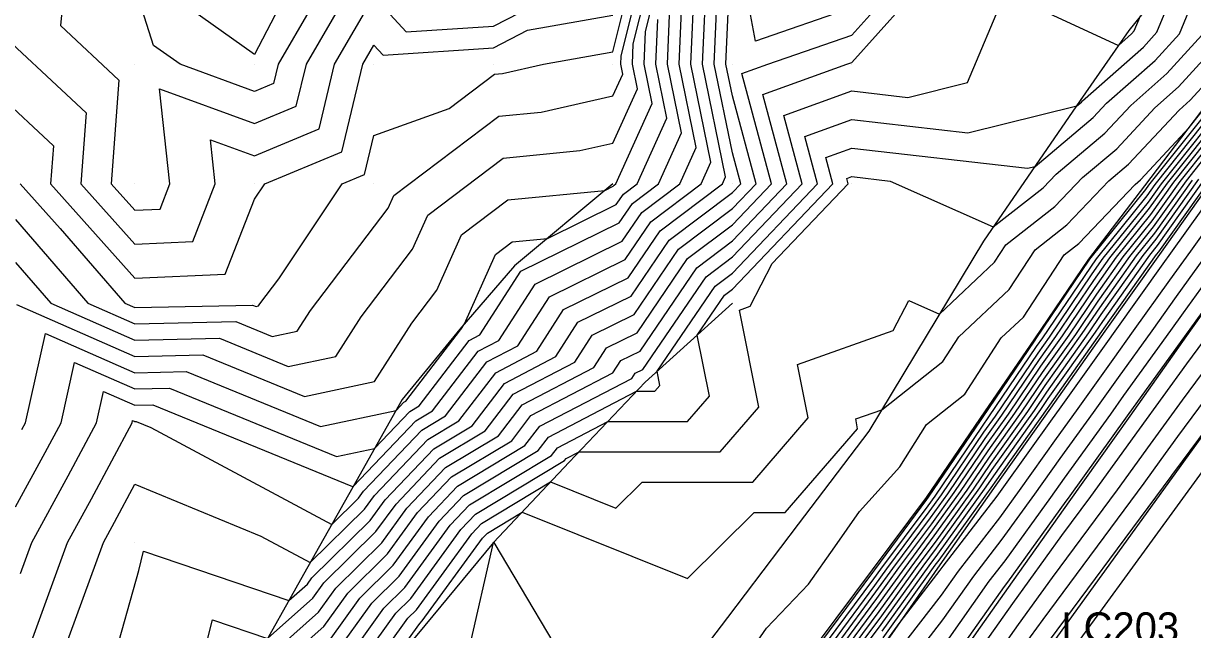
# Model space of a CAD drawing. Extents: x 2188792 to 2191981, y 386090 to 389710.
# Drawn here: x 2190140.8 to 2190238.6, y 387762.9 to 387813.6 of the extents above; entities that cross this region are included whole.
import ezdxf

# ---------------------------------------------------------------- set-up
doc = ezdxf.new("R2010")
doc.units = 0
for name, color, linetype in [('DTM Contours Major', 7, 'Continuous'), ('DTM Contours Minor', 7, 'Continuous'), ('Exist DTM QL2 LIDAR Elevation Point', 7, 'Continuous'), ('Exist Roads EOP', 7, 'Continuous'), ('Exist Roads EOP Cogo Number', 7, 'Continuous'), ('Exist Roads EOT', 7, 'Continuous'), ('PH Exist DTM Breakline', 7, 'Continuous')]:
    doc.layers.add(name, color=color, linetype=linetype)

msp = doc.modelspace()

# ---------------------------------------------------------------- linework, layer by layer
at = {"layer": 'DTM Contours Major'}
for points in [[(2190144.659, 387821.205), (2190143.891, 387813.407), (2190148.79, 387808.85), (2190148.149, 387800.181), (2190150.122, 387797.966), (2190152.238, 387798.064), (2190153.062, 387800.181), (2190152.187, 387808.117), (2190160.123, 387805.211), (2190163.634, 387806.67), (2190164.473, 387810.182), (2190170.124, 387819.904)], [(2190140.121, 387793.604), (2190143.09, 387790.18), (2190150.122, 387787.092), (2190157.192, 387787.249), (2190162.959, 387784.89), (2190166.936, 387785.738), (2190169.059, 387789.052), (2190173.364, 387794.707), (2190174.628, 387797.556), (2190180.952, 387802.329), (2190187.353, 387802.953), (2190190.126, 387803.582), (2190192.176, 387808.131), (2190191.756, 387810.182), (2190191.831, 387811.887), (2190193.9, 387820.182)], [(2190161.758, 387759.424), (2190165.94, 387763.142), (2190167.941, 387765.933), (2190171.266, 387769.214), (2190173.786, 387772.672), (2190176.627, 387775.647), (2190181.657, 387778.683), (2190183.264, 387780.783), (2190190.118, 387784.352), (2190190.785, 387785.392), (2190192.394, 387786.181), (2190197.148, 387793.158), (2190200.127, 387795.407), (2190204.671, 387800.181), (2190202.666, 387807.642), (2190209.704, 387810.182), (2190210.127, 387810.327), (2190218.922, 387820.182)], [(2190141.468, 387761.877), (2190144.498, 387770.178), (2190146.492, 387773.807), (2190149.89, 387780.179), (2190149.932, 387780.368), (2190150.122, 387780.285), (2190150.23, 387780.287), (2190151.458, 387779.785), (2190166.597, 387771.665), (2190168.844, 387773.883), (2190169.259, 387774.453), (2190174.129, 387779.552), (2190176.123, 387780.756), (2190179.579, 387785.27), (2190182.177, 387786.623), (2190184.807, 387790.725), (2190191.153, 387793.839), (2190193.307, 387796.999), (2190197.519, 387800.181), (2190198.329, 387801.978), (2190196.649, 387810.182), (2190196.95, 387817.006)], [(2190168.24, 387757.247), (2190172.953, 387763.82), (2190173.687, 387764.544), (2190178.313, 387770.891), (2190179.125, 387771.741), (2190184.913, 387775.234), (2190190.372, 387773.048), (2190192.575, 387775.223), (2190201.825, 387775.21), (2190206.472, 387780.593), (2190205.586, 387785.062), (2190213.59, 387787.9), (2190214.886, 387790.417), (2190217.447, 387789.267), (2190222.066, 387793.625), (2190223.01, 387795.063), (2190227.116, 387798.278), (2190229.423, 387800.702), (2190232.293, 387803.111), (2190235.478, 387806.533), (2190237.455, 387808.28), (2190241.305, 387812.487)], [(2190208.488, 387761.771), (2190212.052, 387766.571), (2190213.051, 387767.958), (2190216.6, 387772.738), (2190217.615, 387774.148), (2190221.165, 387779.386), (2190222.132, 387780.747), (2190225.7, 387786.014), (2190226.648, 387787.346), (2190230.235, 387792.643), (2190231.164, 387793.948), (2190234.932, 387798.65), (2190236.019, 387800.178), (2190239.618, 387804.692)], [(2190210.876, 387761.68), (2190212.479, 387763.839), (2190215.582, 387768.147), (2190217.111, 387770.206), (2190220.299, 387774.635), (2190221.756, 387776.785), (2190224.85, 387781.136), (2190226.31, 387783.291), (2190229.401, 387787.637), (2190230.864, 387789.797), (2190233.952, 387794.139), (2190235.483, 387796.05), (2190238.64, 387800.489)], [(2190213.956, 387761.034), (2190217.629, 387765.763), (2190219.048, 387767.772), (2190222.492, 387772.237), (2190224.138, 387774.52), (2190227.234, 387778.856), (2190228.916, 387781.187), (2190231.984, 387785.483), (2190233.702, 387787.864), (2190236.74, 387792.119), (2190238.495, 387794.551), (2190241.504, 387798.764)], [(2190246.7, 387794.113), (2190237.768, 387782.084), (2190235.087, 387778.379), (2190232.329, 387774.569), (2190226.891, 387767.239), (2190224.046, 387763.305), (2190221.103, 387759.138)]]:
    msp.add_lwpolyline(points, dxfattribs=at)
at = {"layer": 'DTM Contours Minor'}
for points in [[(2190151.692, 387811.752), (2190148.222, 387822.647), (2190152.051, 387828.254), (2190158.548, 387834.983), (2190163.055, 387823.114), (2190167.602, 387820.182), (2190164.877, 387814.936), (2190162.114, 387810.182), (2190161.73, 387808.574), (2190160.123, 387807.906), (2190153.909, 387810.182), (2190151.692, 387811.752)], [(2190160.123, 387810.995), (2190154.743, 387814.803), (2190152.529, 387821.755), (2190154.973, 387825.333), (2190159.118, 387829.626), (2190161.993, 387822.053), (2190164.895, 387820.182), (2190160.123, 387810.995)], [(2190200.553, 387820.182), (2190206.157, 387824.153), (2190210.127, 387827.386), (2190214.853, 387820.182), (2190210.127, 387814.887), (2190202.051, 387812.106), (2190200.553, 387820.182)], [(2190140.121, 387797.18), (2190146.191, 387790.18), (2190150.122, 387788.454), (2190158.584, 387788.641), (2190161.611, 387787.403), (2190163.699, 387787.848), (2190164.814, 387789.588), (2190171.329, 387798.145), (2190171.799, 387799.205), (2190180.583, 387805.835), (2190184.126, 387806.18), (2190190.126, 387807.542), (2190190.946, 387809.361), (2190190.778, 387810.182), (2190190.808, 387810.864), (2190193.131, 387820.182)], [(2190140.224, 387790.077), (2190150.122, 387785.731), (2190155.8, 387785.857), (2190164.306, 387782.377), (2190170.173, 387783.627), (2190173.304, 387788.517), (2190175.399, 387791.269), (2190177.458, 387795.907), (2190181.322, 387798.823), (2190189.448, 387799.615), (2190190.161, 387799.965), (2190190.234, 387800.072), (2190190.377, 387800.181), (2190193.407, 387806.9), (2190192.735, 387810.182), (2190192.855, 387812.911), (2190194.668, 387820.182)], [(2190140.53, 387800.181), (2190143.878, 387796.423), (2190149.292, 387790.18), (2190150.122, 387789.815), (2190159.977, 387790.034), (2190160.264, 387789.916), (2190160.463, 387789.958), (2190160.568, 387790.123), (2190162.17, 387792.227), (2190167.478, 387800.181), (2190169.347, 387800.958), (2190170.124, 387804.211), (2190176.421, 387806.478), (2190180.213, 387809.34), (2190180.899, 387809.407), (2190184.31, 387810.182), (2190190.126, 387811.209), (2190192.363, 387820.182)], [(2190153.979, 387753.161), (2190156.611, 387763.689), (2190161.217, 387762.12), (2190165.021, 387765.501), (2190165.936, 387766.778), (2190170.297, 387771.082), (2190171.975, 387773.385), (2190175.628, 387777.209), (2190179.443, 387779.512), (2190181.79, 387782.578), (2190186.942, 387785.26), (2190188.394, 387787.525), (2190191.898, 387789.244), (2190195.612, 387794.694), (2190200.127, 387798.105), (2190202.103, 387800.181), (2190200.127, 387807.537), (2190199.585, 387810.182), (2190200.021, 387820.077)], [(2190160.581, 387759.966), (2190165.48, 387764.322), (2190166.939, 387766.355), (2190170.781, 387770.148), (2190172.881, 387773.028), (2190176.127, 387776.428), (2190180.55, 387779.098), (2190182.527, 387781.68), (2190188.53, 387784.806), (2190189.59, 387786.458), (2190192.146, 387787.712), (2190196.38, 387793.926), (2190200.127, 387796.756), (2190203.387, 387800.181), (2190200.911, 387809.398), (2190203.083, 387810.182), (2190210.127, 387812.607), (2190216.888, 387820.182)], [(2190146.165, 387752.534), (2190150.45, 387767.809), (2190150.858, 387769.441), (2190163.01, 387765.301), (2190164.561, 387766.68), (2190164.934, 387767.2), (2190169.812, 387772.016), (2190171.07, 387773.741), (2190175.128, 387777.99), (2190178.336, 387779.927), (2190181.053, 387783.475), (2190185.353, 387785.714), (2190187.198, 387788.592), (2190191.65, 387790.776), (2190194.844, 387795.463), (2190200.127, 387799.453), (2190200.819, 387800.181), (2190200.127, 387802.759), (2190198.606, 387810.182), (2190198.997, 387819.053)], [(2190166.86, 387760.784), (2190169.946, 387765.087), (2190172.234, 387767.346), (2190175.597, 387771.959), (2190177.626, 387774.084), (2190183.87, 387777.853), (2190184.738, 387778.988), (2190192.093, 387782.817), (2190193.639, 387782.815), (2190194.064, 387783.307), (2190193.829, 387784.495), (2190198.685, 387791.621), (2190200.127, 387792.71), (2190207.24, 387800.181), (2190206.178, 387804.13), (2190210.127, 387805.555), (2190219.818, 387804.441), (2190228.935, 387806.69), (2190229.326, 387807.019), (2190229.417, 387807.116), (2190234.513, 387811.618), (2190235.644, 387812.855), (2190238.182, 387818.993)], [(2190142.392, 387756.181), (2190147.502, 387770.178), (2190148.431, 387771.868), (2190150.122, 387775.039), (2190160.674, 387770.698), (2190164.804, 387768.483), (2190169.328, 387772.95), (2190170.164, 387774.097), (2190174.628, 387778.771), (2190177.23, 387780.342), (2190180.316, 387784.373), (2190183.765, 387786.169), (2190186.003, 387789.659), (2190191.401, 387792.307), (2190194.075, 387796.231), (2190199.304, 387800.181), (2190199.56, 387800.747), (2190197.628, 387810.182), (2190197.973, 387818.029)], [(2190167.32, 387759.605), (2190170.949, 387764.665), (2190172.719, 387766.412), (2190176.502, 387771.603), (2190178.126, 387773.303), (2190184.977, 387777.439), (2190185.476, 387778.09), (2190189.699, 387780.289), (2190196.368, 387780.28), (2190198.2, 387782.402), (2190197.185, 387787.524), (2190199.453, 387790.853), (2190200.127, 387791.362), (2190208.524, 387800.181), (2190207.934, 387802.374), (2190210.127, 387803.165), (2190224.824, 387801.476), (2190225.447, 387801.63), (2190230.315, 387805.716), (2190231.437, 387806.922), (2190235.494, 387810.505), (2190237.531, 387812.732), (2190239.496, 387817.484)], [(2190137.358, 387814.19), (2190146.048, 387806.107), (2190145.609, 387800.181), (2190150.122, 387795.117), (2190154.962, 387795.341), (2190156.846, 387800.181), (2190156.44, 387803.864), (2190160.123, 387802.515), (2190165.538, 387804.766), (2190166.832, 387810.182), (2190170.124, 387815.846), (2190172.828, 387812.886), (2190180.125, 387813.368), (2190186.713, 387816.77)], [(2190140.543, 387767.574), (2190141.494, 387770.178), (2190144.554, 387775.746), (2190146.917, 387780.179), (2190147.505, 387782.795), (2190150.122, 387781.646), (2190151.623, 387781.68), (2190168.348, 387774.839), (2190168.39, 387774.847), (2190173.629, 387780.334), (2190175.016, 387781.171), (2190178.842, 387786.168), (2190180.588, 387787.077), (2190183.611, 387791.792), (2190190.905, 387795.37), (2190192.539, 387797.768), (2190195.734, 387800.181), (2190197.099, 387803.209), (2190195.671, 387810.182), (2190195.926, 387815.982)], [(2190166.4, 387761.963), (2190168.944, 387765.51), (2190171.75, 387768.28), (2190174.692, 387772.316), (2190177.126, 387774.865), (2190182.763, 387778.268), (2190184.001, 387779.885), (2190191.707, 387783.897), (2190191.981, 387784.325), (2190192.642, 387784.649), (2190197.917, 387792.39), (2190200.127, 387794.059), (2190205.956, 387800.181), (2190204.422, 387805.886), (2190210.127, 387807.945), (2190214.813, 387807.406), (2190219.805, 387808.638), (2190222.939, 387816.157), (2190232.422, 387811.751), (2190233.532, 387812.731), (2190233.757, 387812.977), (2190234.271, 387814.22)], [(2190140.121, 387773.146), (2190142.615, 387777.685), (2190143.945, 387780.179), (2190145.078, 387785.222), (2190150.122, 387783.008), (2190153.015, 387783.072), (2190167, 387777.351), (2190170.183, 387778.029), (2190173.129, 387781.115), (2190173.909, 387781.586), (2190178.105, 387787.065), (2190179, 387787.531), (2190182.416, 387792.859), (2190190.657, 387796.902), (2190191.77, 387798.536), (2190193.948, 387800.181), (2190195.868, 387804.439), (2190194.692, 387810.182), (2190194.902, 387814.958)], [(2190138.637, 387807.707), (2190143.305, 387803.365), (2190143.069, 387800.181), (2190150.122, 387792.267), (2190157.685, 387792.617), (2190160.123, 387798.878), (2190160.992, 387800.181), (2190167.443, 387802.862), (2190169.191, 387810.182), (2190170.124, 387811.787), (2190170.89, 387810.948), (2190180.125, 387811.557), (2190182.97, 387813.027), (2190190.126, 387814.291)], [(2190140.676, 387779.623), (2190140.972, 387780.179), (2190142.651, 387787.649), (2190150.122, 387784.369), (2190154.407, 387784.464), (2190165.653, 387779.864), (2190171.976, 387781.211), (2190172.63, 387781.896), (2190172.803, 387782.001), (2190177.368, 387787.963), (2190177.412, 387787.986), (2190177.71, 387788.45), (2190180.288, 387794.258), (2190181.692, 387795.317), (2190184.644, 387795.605), (2190190.409, 387798.433), (2190191.002, 387799.304), (2190192.163, 387800.181), (2190194.638, 387805.67), (2190193.713, 387810.182), (2190193.879, 387813.935)], [(2190167.78, 387758.426), (2190171.951, 387764.242), (2190173.203, 387765.478), (2190177.408, 387771.247), (2190178.625, 387772.522), (2190186.083, 387777.024), (2190186.213, 387777.193), (2190187.306, 387777.762), (2190199.097, 387777.745), (2190202.336, 387781.497), (2190200.727, 387789.617), (2190201.606, 387789.929), (2190203.442, 387793.495), (2190209.808, 387800.181), (2190209.69, 387800.618), (2190210.127, 387800.776), (2190213.318, 387800.409), (2190221.96, 387796.57), (2190226.117, 387799.825), (2190227.226, 387800.991), (2190231.304, 387804.414), (2190233.457, 387806.727), (2190236.474, 387809.393), (2190239.418, 387812.609)], [(2190170.264, 387758.25), (2190173.956, 387763.397), (2190174.172, 387763.611), (2190179.219, 387770.534), (2190179.625, 387770.959), (2190182.519, 387772.707), (2190196.367, 387767.162), (2190201.957, 387772.679), (2190204.554, 387772.676), (2190210.607, 387779.688), (2190210.445, 387780.507), (2190212.62, 387781.278), (2190217.745, 387785.316), (2190219.076, 387787.369), (2190223.273, 387791.328), (2190225.449, 387794.643), (2190228.115, 387796.731), (2190231.619, 387800.413), (2190233.282, 387801.808), (2190237.498, 387806.338), (2190238.436, 387807.167), (2190243.192, 387812.364)], [(2190201.094, 387760.265), (2190202.983, 387762.997), (2190206.493, 387766.666), (2190208.692, 387769.803), (2190210.761, 387772.756), (2190214.135, 387776.487), (2190216.369, 387780.045), (2190219.57, 387782.567), (2190222.628, 387787.285), (2190224.479, 387789.03), (2190227.889, 387794.223), (2190229.115, 387795.184), (2190233.816, 387800.124), (2190234.27, 387800.505), (2190238.353, 387804.891), (2190239.33, 387806.116)], [(2190207.533, 387761.808), (2190211.881, 387767.664), (2190212.038, 387767.882), (2190216.396, 387773.751), (2190216.542, 387773.954), (2190220.928, 387780.427), (2190221.045, 387780.591), (2190225.456, 387787.103), (2190225.547, 387787.23), (2190229.984, 387793.782), (2190230.048, 387793.872), (2190234.712, 387799.69), (2190234.97, 387800.053), (2190239.426, 387805.642)], [(2190208.011, 387761.79), (2190211.966, 387767.118), (2190212.544, 387767.92), (2190216.498, 387773.244), (2190217.079, 387774.051), (2190221.047, 387779.907), (2190221.588, 387780.669), (2190225.578, 387786.558), (2190226.098, 387787.288), (2190230.11, 387793.212), (2190230.606, 387793.91), (2190234.822, 387799.17), (2190235.494, 387800.116), (2190239.522, 387805.167)], [(2190208.966, 387761.753), (2190212.137, 387766.025), (2190213.557, 387767.996), (2190216.702, 387772.231), (2190218.152, 387774.246), (2190221.283, 387778.866), (2190222.676, 387780.824), (2190225.822, 387785.469), (2190227.199, 387787.405), (2190230.361, 387792.074), (2190231.721, 387793.986), (2190235.042, 387798.13), (2190236.543, 387800.24), (2190239.714, 387804.217)], [(2190209.443, 387761.735), (2190212.223, 387765.478), (2190214.063, 387768.033), (2190216.804, 387771.725), (2190218.689, 387774.343), (2190221.401, 387778.346), (2190223.219, 387780.902), (2190225.944, 387784.924), (2190227.749, 387787.463), (2190230.487, 387791.505), (2190232.279, 387794.024), (2190235.153, 387797.61), (2190237.067, 387800.302), (2190239.81, 387803.742)], [(2190209.921, 387761.717), (2190212.308, 387764.932), (2190214.57, 387768.071), (2190216.907, 387771.219), (2190219.226, 387774.441), (2190221.519, 387777.825), (2190223.763, 387780.98), (2190226.066, 387784.38), (2190228.3, 387787.521), (2190230.612, 387790.935), (2190232.837, 387794.063), (2190235.263, 387797.09), (2190237.592, 387800.365), (2190239.906, 387803.267)], [(2190210.399, 387761.698), (2190212.393, 387764.385), (2190215.076, 387768.109), (2190217.009, 387770.712), (2190219.762, 387774.538), (2190221.637, 387777.305), (2190224.307, 387781.058), (2190226.188, 387783.835), (2190228.85, 387787.579), (2190230.738, 387790.366), (2190233.394, 387794.101), (2190235.373, 387796.57), (2190238.116, 387800.427), (2190240.002, 387802.793)], [(2190212.735, 387762.199), (2190217.101, 387768.26), (2190217.417, 387768.686), (2190221.909, 387774.928), (2190222.11, 387775.224), (2190226.481, 387781.37), (2190226.675, 387781.657), (2190231.053, 387787.812), (2190231.241, 387788.089), (2190235.625, 387794.253), (2190235.814, 387794.489), (2190240.214, 387800.676)], [(2190211.354, 387761.662), (2190212.564, 387763.292), (2190216.088, 387768.185), (2190217.213, 387769.699), (2190220.836, 387774.733), (2190221.874, 387776.264), (2190225.394, 387781.214), (2190226.432, 387782.746), (2190229.952, 387787.696), (2190230.989, 387789.228), (2190234.51, 387794.177), (2190235.594, 387795.53), (2190239.165, 387800.551)], [(2190212.65, 387762.746), (2190216.595, 387768.222), (2190217.315, 387769.193), (2190221.373, 387774.83), (2190221.992, 387775.744), (2190225.937, 387781.292), (2190226.553, 387782.201), (2190230.502, 387787.754), (2190231.115, 387788.658), (2190235.067, 387794.215), (2190235.704, 387795.01), (2190239.689, 387800.614)], [(2190212.82, 387761.653), (2190214.159, 387763.512), (2190217.521, 387767.839), (2190217.774, 387768.197), (2190222.278, 387774.037), (2190222.842, 387774.819), (2190226.908, 387780.512), (2190227.497, 387781.329), (2190231.542, 387786.994), (2190232.158, 387787.847), (2190236.183, 387793.483), (2190236.825, 387794.372), (2190240.828, 387799.978)], [(2190224.536, 387761.542), (2190226.123, 387763.736), (2190234.571, 387775.124), (2190236.01, 387777.112), (2190237.408, 387779.043), (2190250.996, 387797.344)], [(2190241.836, 387794.908), (2190237.856, 387789.391), (2190236.789, 387787.897), (2190232.866, 387782.46), (2190231.754, 387780.902), (2190227.888, 387775.542), (2190226.731, 387773.922), (2190222.92, 387768.638), (2190221.595, 387766.921), (2190217.846, 387761.61)], [(2190243.506, 387795.087), (2190238.413, 387788.027), (2190238.333, 387787.914), (2190233.308, 387780.948), (2190233.173, 387780.76), (2190228.215, 387773.886), (2190228.027, 387773.623), (2190223.134, 387766.839), (2190222.869, 387766.495), (2190217.954, 387759.534)], [(2190215.192, 387760.409), (2190217.737, 387763.686), (2190220.322, 387767.346), (2190222.706, 387770.438), (2190225.434, 387774.221), (2190227.561, 387777.199), (2190230.335, 387781.044), (2190232.425, 387783.971), (2190235.245, 387787.881), (2190237.298, 387790.755), (2190240.165, 387794.729)], [(2190242.404, 387790.882), (2190238.128, 387785.124), (2190234.164, 387779.647), (2190230.086, 387774.013), (2190227.659, 387770.741), (2190223.556, 387765.067), (2190219.311, 387759.057)], [(2190243.23, 387784.33), (2190237.048, 387776.003), (2190236.932, 387775.844), (2190236.814, 387775.68), (2190225.355, 387760.234)], [(2190178.103, 387761.247), (2190180.12, 387770.172), (2190180.124, 387770.178), (2190180.124, 387770.178)], [(2190180.124, 387770.178), (2190180.126, 387770.179), (2190180.147, 387770.171), (2190180.149, 387770.153), (2190187.392, 387758.002)]]:
    msp.add_lwpolyline(points, dxfattribs=at)
at = {"layer": 'Exist DTM QL2 LIDAR Elevation Point'}
for p, q in [((2190150.122, 387810.182), (2190150.122, 387810.182)), ((2190160.123, 387810.182), (2190160.123, 387810.182)), ((2190170.124, 387810.182), (2190170.124, 387810.182)), ((2190180.125, 387810.182), (2190180.125, 387810.182)), ((2190190.126, 387810.182), (2190190.126, 387810.182)), ((2190200.127, 387810.182), (2190200.127, 387810.182)), ((2190210.127, 387810.182), (2190210.127, 387810.182)), ((2190150.122, 387800.181), (2190150.122, 387800.181)), ((2190160.123, 387800.181), (2190160.123, 387800.181)), ((2190170.124, 387800.181), (2190170.124, 387800.181)), ((2190200.127, 387800.181), (2190200.127, 387800.181)), ((2190210.127, 387800.181), (2190210.127, 387800.181)), ((2190150.122, 387790.18), (2190150.122, 387790.18)), ((2190160.123, 387790.18), (2190160.123, 387790.18)), ((2190150.122, 387780.179), (2190150.122, 387780.179)), ((2190150.122, 387770.178), (2190150.122, 387770.178))]:
    msp.add_line(p, q, dxfattribs=at)
at = {"layer": 'Exist Roads EOP'}
msp.add_lwpolyline([(2190313.986, 387884.141), (2190285.547, 387843.636), (2190254.588, 387800.045), (2190225.155, 387759.32), (2190194.829, 387717.425), (2190164.291, 387675.101), (2190137.229, 387637.301), (2190105.098, 387592.774), (2190071.411, 387546.221), (2190039.296, 387501.568), (2190007.542, 387457.958), (2189976.844, 387415.407), (2189936.359, 387359.145), (2189907.138, 387318.716), (2189868.636, 387265.243), (2189836.428, 387220.463), (2189805.695, 387177.815), (2189775.592, 387135.957), (2189745.498, 387094.055), (2189715.496, 387052.249), (2189683.869, 387008.07), (2189653.218, 386965.867), (2189623.729, 386924.667)], dxfattribs=at)
at = {"layer": 'Exist Roads EOT'}
msp.add_lwpolyline([(2189910.407, 387320.236), (2189942.075, 387364.22), (2189970.438, 387403.768), (2190000.916, 387446.161), (2190032.053, 387489.248), (2190063.107, 387532.142), (2190093.978, 387574.79), (2190125.104, 387617.946), (2190155.102, 387659.638), (2190185.949, 387702.484), (2190216.886, 387745.11), (2190247.602, 387787.3), (2190276.876, 387828.015), (2190303.928, 387865.67), (2190323.039, 387892.195)], dxfattribs=at)
at = {"layer": 'PH Exist DTM Breakline'}
for points in [[(2190180.541, 387728.105), (2190185.164, 387730.913), (2190189.547, 387737.179), (2190193.93, 387743.444), (2190198.312, 387749.71), (2190202.825, 387755.762), (2190207.337, 387761.815), (2190211.849, 387767.868), (2190216.361, 387773.921), (2190220.896, 387780.569), (2190225.431, 387787.218), (2190229.965, 387793.866), (2190234.643, 387800.015), (2190239.32, 387806.163), (2190243.998, 387812.312), (2190248.218, 387818.171), (2190252.438, 387824.03), (2190256.658, 387829.889), (2190260.816, 387836.07), (2190265.791, 387842.926), (2190270.765, 387849.782)], [(2190276.671, 387848.261), (2190271.748, 387840.263), (2190267.321, 387835.092), (2190262.893, 387829.922), (2190257.613, 387823.753), (2190252.334, 387817.584), (2190248.364, 387811.956), (2190244.395, 387806.329), (2190240.426, 387800.701), (2190235.861, 387794.269), (2190231.296, 387787.838), (2190226.731, 387781.406), (2190222.167, 387774.974), (2190217.497, 387768.29), (2190212.828, 387761.606), (2190208.158, 387754.921), (2190203.489, 387748.237), (2190198.82, 387741.552), (2190193.128, 387733.515), (2190186.991, 387724.396)], [(2190253.244, 387838.588), (2190250.301, 387834.059), (2190247.709, 387830.205), (2190243.031, 387825.029), (2190238.16, 387819.018), (2190233.288, 387813.008), (2190229.24, 387807.133), (2190225.191, 387801.258), (2190221.143, 387795.384), (2190216.339, 387787.434), (2190211.536, 387779.485), (2190205.619, 387771.686), (2190199.702, 387763.888), (2190193.786, 387756.089)], [(2190267.624, 387828.086), (2190262.809, 387821.487), (2190257.994, 387814.888), (2190253.179, 387808.289), (2190248.364, 387801.69), (2190243.55, 387795.091), (2190238.459, 387787.916), (2190233.369, 387780.74), (2190228.278, 387773.565), (2190223.188, 387766.389), (2190217.982, 387758.998), (2190212.776, 387751.606), (2190207.57, 387744.215), (2190202.364, 387736.823), (2190197.159, 387729.432), (2190192.781, 387722.608)], [(2190190.126, 387800.181), (2190181.902, 387793.317), (2190177.329, 387788.009), (2190172.487, 387782.119), (2190168.366, 387774.805), (2190164.244, 387767.491), (2190160.123, 387760.177), (2190152.684, 387751.682)], [(2190200.127, 387790.18), (2190192.815, 387783.58), (2190186.47, 387776.879), (2190180.125, 387770.178), (2190174.374, 387763.221), (2190168.623, 387756.265), (2190163.895, 387750.516), (2190161.531, 387747.641)]]:
    msp.add_lwpolyline(points, dxfattribs=at)

# ---------------------------------------------------------------- texts
at = {"layer": 'Exist Roads EOP Cogo Number'}
msp.add_text('LC203', height=2.5, dxfattribs=at).set_placement((2190227.655, 387761.82))

doc.saveas('drawing.dxf')
